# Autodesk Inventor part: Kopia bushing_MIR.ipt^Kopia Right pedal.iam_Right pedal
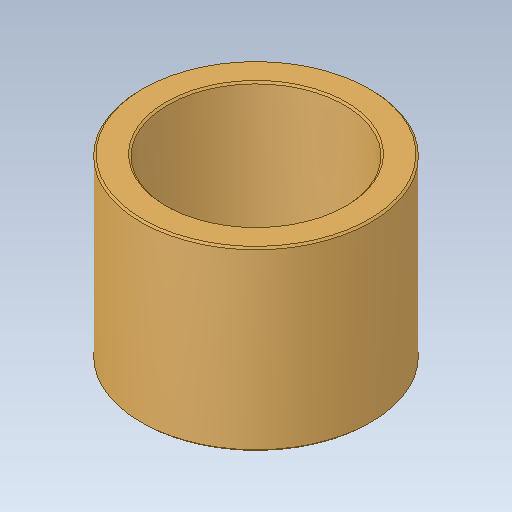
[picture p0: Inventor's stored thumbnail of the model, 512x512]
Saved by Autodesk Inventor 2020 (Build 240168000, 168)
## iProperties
Created: 2017-10
Part Number: Kopia bushing_MIR.ipt^Kopia Right pedal.iam_Right pedal
Material: solidworks materials|Mosiądz|27
Document SubType Name: Modeling
Designer: Tomasz
Appearance: 0,0,0
Sending System: SolidWorks 2017
Last Author: Tomasz
Last Saved: 2017-11-19
Author: Tomasz
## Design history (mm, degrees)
feature "bushing_MIR.ipt"
node "Bryła1"
